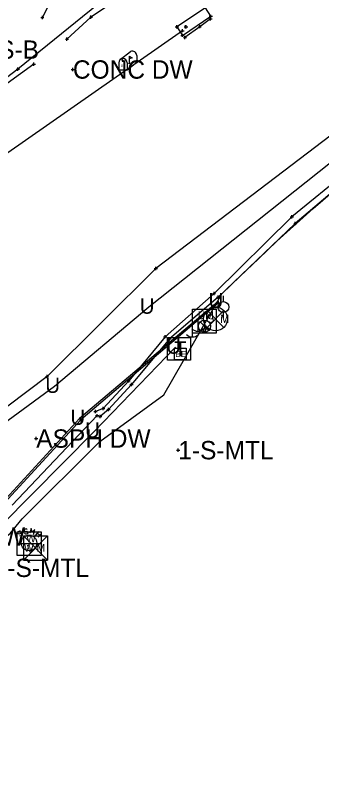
# Model space of a CAD drawing. Extents: x -1 to 1157254, y -1 to 2021979.
# Drawn here: x 1146610.6 to 1146731, y 2016480.3 to 2016780.3 of the extents above; entities that cross this region are included whole.
import ezdxf

# ---------------------------------------------------------------- set-up
doc = ezdxf.new("R2010")
doc.units = 0
for name, color, linetype in [('S_BUILDING_ANNOT', 7, 'Continuous'), ('S_CAL_CORNER', 7, 'Continuous'), ('S_CAL_CORNER_ANNOT', 7, 'Continuous'), ('S_CATCH_BASIN', 7, 'Continuous'), ('S_CATCH_BASIN_ANNOT', 7, 'Continuous'), ('S_CONTOUR_ANNOT', 7, 'Continuous'), ('S_CONTOUR_MAJOR', 7, 'Continuous'), ('S_CROSS_DRAIN', 7, 'Continuous'), ('S_CROSS_DRAIN_ANNOT', 7, 'Continuous'), ('S_CTL_TABLE', 7, 'Continuous'), ('S_DITCHLINE', 7, 'Continuous'), ('S_DRIVEWAY', 7, 'Continuous'), ('S_DRIVEWAY_ANNOT', 7, 'Continuous'), ('S_DROP_INLET', 7, 'Continuous'), ('S_DROP_INLET_ANNOT', 7, 'Continuous'), ('S_EDGE_BITUMINOUS_ANNOT', 7, 'Continuous'), ('S_ELECTRIC_UTILITIES', 7, 'Continuous'), ('S_FENCE', 7, 'Continuous'), ('S_GAS_PUMP_ISLAND_ANNOT', 7, 'Continuous'), ('S_GATE', 7, 'Continuous')]:
    doc.layers.add(name, color=color, linetype=linetype)

msp = doc.modelspace()

# ---------------------------------------------------------------- linework, layer by layer
at = {"layer": 'S_BUILDING_ANNOT'}
for p, q in [((1146686.78, 2016779.94), (1146688.05, 2016779.94)), ((1146687.42, 2016779.3), (1146687.42, 2016780.58)), ((1146687.42, 2016779.94), (1146687.42, 2016779.94)), ((1146673.47, 2016775.77), (1146674.74, 2016775.77)), ((1146674.11, 2016775.13), (1146674.1, 2016776.41)), ((1146674.1, 2016775.77), (1146674.1, 2016775.77)), ((1146676.9, 2016775.8), (1146678.18, 2016775.8)), ((1146677.1, 2016775.77), (1146678.37, 2016775.77)), ((1146677.54, 2016775.16), (1146677.54, 2016776.44)), ((1146677.54, 2016775.8), (1146677.54, 2016775.8)), ((1146677.73, 2016775.14), (1146677.73, 2016776.41)), ((1146677.73, 2016775.77), (1146677.73, 2016775.77)), ((1146675.61, 2016772.46), (1146676.89, 2016772.47)), ((1146675.71, 2016774.31), (1146676.98, 2016774.31)), ((1146676.25, 2016771.83), (1146676.25, 2016773.1)), ((1146676.25, 2016772.46), (1146676.25, 2016772.46)), ((1146676.35, 2016773.67), (1146676.34, 2016774.95)), ((1146676.34, 2016774.31), (1146676.34, 2016774.31)), ((1146610.94, 2016759.23), (1146612.21, 2016759.23)), ((1146611.58, 2016758.59), (1146611.58, 2016759.87)), ((1146611.58, 2016759.23), (1146611.58, 2016759.23)), ((1146632.59, 2016759.06), (1146633.86, 2016759.07)), ((1146633.23, 2016758.43), (1146633.22, 2016759.7)), ((1146633.23, 2016759.07), (1146633.23, 2016759.07)), ((1146718.66, 2016701.25), (1146719.93, 2016701.25)), ((1146719.29, 2016700.61), (1146719.29, 2016701.88)), ((1146719.29, 2016701.25), (1146719.29, 2016701.25)), ((1146720.02, 2016698.6), (1146721.29, 2016698.61)), ((1146720.66, 2016697.97), (1146720.65, 2016699.24)), ((1146720.65, 2016698.61), (1146720.65, 2016698.61)), ((1146665.18, 2016680.99), (1146666.45, 2016681)), ((1146665.82, 2016680.36), (1146665.81, 2016681.63)), ((1146665.82, 2016680.99), (1146665.82, 2016680.99)), ((1146688.06, 2016671.14), (1146689.33, 2016671.15)), ((1146688.7, 2016670.51), (1146688.69, 2016671.78)), ((1146688.69, 2016671.14), (1146688.69, 2016671.14)), ((1146690.36, 2016669.05), (1146690.35, 2016670.33)), ((1146689.72, 2016669.69), (1146690.99, 2016669.69)), ((1146689.81, 2016667.45), (1146691.08, 2016667.46)), ((1146690.36, 2016669.69), (1146690.36, 2016669.69)), ((1146690.44, 2016666.82), (1146690.44, 2016668.09)), ((1146690.44, 2016667.45), (1146690.44, 2016667.45)), ((1146668.85, 2016654.2), (1146670.12, 2016654.2)), ((1146669.49, 2016653.57), (1146669.48, 2016654.84)), ((1146669.49, 2016654.2), (1146669.49, 2016654.2)), ((1146670.57, 2016653.4), (1146671.84, 2016653.4)), ((1146671.21, 2016652.76), (1146671.2, 2016654.04)), ((1146671.2, 2016653.4), (1146671.2, 2016653.4)), ((1146622.43, 2016638.6), (1146623.7, 2016638.6)), ((1146623.06, 2016637.96), (1146623.06, 2016639.23)), ((1146623.06, 2016638.6), (1146623.06, 2016638.6)), ((1146655.16, 2016636.19), (1146655.16, 2016637.46)), ((1146654.52, 2016636.82), (1146655.8, 2016636.83)), ((1146655.16, 2016636.82), (1146655.16, 2016636.82)), ((1146655.67, 2016635.42), (1146656.94, 2016635.42)), ((1146656.3, 2016634.79), (1146656.3, 2016636.06)), ((1146656.3, 2016635.42), (1146656.3, 2016635.42)), ((1146642.12, 2016624.24), (1146642.12, 2016625.51)), ((1146644.54, 2016626.05), (1146645.81, 2016626.05)), ((1146645.18, 2016625.41), (1146645.17, 2016626.68)), ((1146645.17, 2016626.05), (1146645.17, 2016626.05)), ((1146646.6, 2016625.66), (1146647.88, 2016625.66)), ((1146647.24, 2016625.03), (1146647.24, 2016626.3)), ((1146647.24, 2016625.66), (1146647.24, 2016625.66)), ((1146636.41, 2016620.93), (1146636.41, 2016622.2)), ((1146641.49, 2016624.87), (1146642.76, 2016624.88)), ((1146642.12, 2016624.87), (1146642.12, 2016624.87)), ((1146642.17, 2016623.21), (1146643.44, 2016623.21)), ((1146642.81, 2016622.57), (1146642.8, 2016623.85)), ((1146642.8, 2016623.21), (1146642.8, 2016623.21)), ((1146643.35, 2016622.84), (1146644.62, 2016622.84)), ((1146643.98, 2016622.21), (1146643.98, 2016623.48)), ((1146643.98, 2016622.84), (1146643.98, 2016622.84)), ((1146635.77, 2016621.57), (1146637.04, 2016621.57)), ((1146636.41, 2016621.57), (1146636.41, 2016621.57)), ((1146618.19, 2016614.22), (1146619.46, 2016614.23)), ((1146618.83, 2016613.59), (1146618.82, 2016614.86)), ((1146618.82, 2016614.22), (1146618.82, 2016614.22)), ((1146674.65, 2016609.02), (1146674.65, 2016610.29)), ((1146674.01, 2016609.65), (1146675.29, 2016609.66)), ((1146674.65, 2016609.66), (1146674.65, 2016609.66))]:
    msp.add_line(p, q, dxfattribs=at)
at = {"layer": 'S_CAL_CORNER'}
for p, q in [((1146683.28, 2016659.99), (1146686.61, 2016656.65)), ((1146684.79, 2016660.21), (1146685.1, 2016660.21)), ((1146684.95, 2016658.32), (1146684.95, 2016660.05)), ((1146684.95, 2016658.32), (1146684.95, 2016657.26)), ((1146684.35, 2016657.42), (1146684.35, 2016657.23)), ((1146685.54, 2016657.42), (1146685.55, 2016657.19))]:
    msp.add_line(p, q, dxfattribs=at)
msp.add_lwpolyline([(1146680.18, 2016664.98), (1146689.59, 2016664.98), (1146689.59, 2016655.57), (1146680.18, 2016655.57)], close=True, dxfattribs=at)
msp.add_circle((1146684.95, 2016658.32), 2.36, dxfattribs=at)
for centre, radius, start, end in [((1146684.95, 2016660.21), 0.156, 180, 0), ((1146684.77, 2016657.81), 0.58, 223.1344, 287.472), ((1146685.12, 2016657.82), 0.58, 252.528, 316.8656)]:
    msp.add_arc(centre, radius, start, end, dxfattribs=at)
msp.add_ellipse((1146684.95, 2016657.07), major_axis=(0, -0.82), ratio=0.744362, start_param=4.519801, end_param=8.000179, dxfattribs=at)
at = {"layer": 'S_CAL_CORNER_ANNOT'}
for p, q in [((1146685.98, 2016657.87), (1146692.6, 2016664.48)), ((1146685.98, 2016664.48), (1146692.6, 2016657.87))]:
    msp.add_line(p, q, dxfattribs=at)
msp.add_lwpolyline([(1146788.73, 2016902.43), (1146611.58, 2016759.23), (1146520.07, 2016689.4), (1146406.59, 2016626.1)], dxfattribs=at)
msp.add_circle((1146689.29, 2016661.18), 4.68, dxfattribs=at)
at = {"layer": 'S_CATCH_BASIN'}
for p, q in [((1146692.36, 2016667.94), (1146692.36, 2016670.19)), ((1146690.27, 2016665.81), (1146687.95, 2016665.81)), ((1146682.3, 2016661.07), (1146682.3, 2016656.34)), ((1146692.44, 2016661.4), (1146692.44, 2016663.72)), ((1146680.16, 2016658.81), (1146680.16, 2016654.08))]:
    msp.add_line(p, q, dxfattribs=at)
msp.add_circle((1146692.36, 2016665.83), 2.13, dxfattribs=at)
for centre in [(1146680.22, 2016657.51), (1146682.36, 2016659.77)]:
    msp.add_arc(centre, 3.41, 226.3972, 313.6028, dxfattribs=at)
at = {"layer": 'S_CATCH_BASIN_ANNOT'}
msp.add_lwpolyline([(1146670.42, 2016644.93), (1146670.42, 2016653.93), (1146679.42, 2016653.93), (1146679.42, 2016644.93)], close=True, dxfattribs=at)
at = {"layer": 'S_CONTOUR_ANNOT'}
for p, q in [((1146611.33, 2016577.67), (1146620.74, 2016577.67)), ((1146611.33, 2016568.26), (1146611.33, 2016577.67)), ((1146620.74, 2016577.67), (1146620.74, 2016568.26)), ((1146613.86, 2016576.02), (1146623.2, 2016576.02)), ((1146613.86, 2016576.02), (1146613.86, 2016566.53)), ((1146613.86, 2016576.02), (1146623.2, 2016566.53)), ((1146623.2, 2016576.02), (1146613.86, 2016566.53)), ((1146623.2, 2016576.02), (1146623.2, 2016566.53)), ((1146611.33, 2016572.99), (1146620.74, 2016572.99)), ((1146620.74, 2016568.26), (1146611.33, 2016568.26)), ((1146613.86, 2016566.53), (1146623.2, 2016566.53))]:
    msp.add_line(p, q, dxfattribs=at)
at = {"layer": 'S_CROSS_DRAIN'}
for p, q in [((1146651.78, 2016762.97), (1146655.91, 2016766.08)), ((1146655.39, 2016764.26), (1146655.39, 2016761.54)), ((1146658.34, 2016764.6), (1146658.34, 2016761.89)), ((1146651.23, 2016761.69), (1146651.23, 2016758.98)), ((1146654.55, 2016758.98), (1146658.34, 2016761.89)), ((1146654.55, 2016761.69), (1146654.55, 2016758.98)), ((1146651.23, 2016758.98), (1146654.55, 2016758.98))]:
    msp.add_line(p, q, dxfattribs=at)
for points in [[(1146655.39, 2016764.26), (1146656.5, 2016763.59), (1146655.39, 2016763.25)], [(1146652.41, 2016762.81), (1146652.63, 2016762.67), (1146652.63, 2016762.28), (1146652.94, 2016762.28), (1146652.94, 2016762.64), (1146652.74, 2016762.89), (1146652.41, 2016762.84)]]:
    msp.add_lwpolyline(points, dxfattribs=at)
for centre, end in [((1146656.68, 2016764.6), 117.5718), ((1146652.89, 2016761.69), 180)]:
    msp.add_arc(centre, 1.66, 0, end, dxfattribs=at)
msp.add_ellipse((1146655.39, 2016761.54), major_axis=(0.145, 0.132), ratio=0.564646, dxfattribs=at)
at = {"layer": 'S_CROSS_DRAIN_ANNOT'}
msp.add_lwpolyline([(1146673.19, 2016645.15), (1146673.19, 2016649.65), (1146677.69, 2016649.65), (1146677.69, 2016645.15)], close=True, dxfattribs=at)
at = {"layer": 'S_CTL_TABLE'}
for p, q in [((1146620.59, 2016779.5), (1146621.86, 2016779.5)), ((1146621.23, 2016778.86), (1146621.22, 2016780.14)), ((1146621.23, 2016779.5), (1146621.23, 2016779.5)), ((1146639.71, 2016779.66), (1146640.98, 2016779.66)), ((1146640.34, 2016779.02), (1146640.34, 2016780.3)), ((1146640.34, 2016779.66), (1146640.34, 2016779.66)), ((1146686.69, 2016778.92), (1146687.96, 2016778.93)), ((1146687.33, 2016778.29), (1146687.33, 2016779.56)), ((1146687.33, 2016778.93), (1146687.33, 2016778.93)), ((1146682.43, 2016775.87), (1146683.7, 2016775.87)), ((1146683.07, 2016775.23), (1146683.07, 2016776.51)), ((1146683.07, 2016775.87), (1146683.07, 2016775.87)), ((1146677.28, 2016770.99), (1146677.27, 2016772.26)), ((1146630.26, 2016770.98), (1146631.54, 2016770.98)), ((1146630.9, 2016770.35), (1146630.9, 2016771.62)), ((1146630.9, 2016770.98), (1146630.9, 2016770.98)), ((1146676.64, 2016771.62), (1146677.91, 2016771.63)), ((1146677.28, 2016771.62), (1146677.28, 2016771.62)), ((1146617.21, 2016761.13), (1146618.48, 2016761.13)), ((1146617.85, 2016760.49), (1146617.84, 2016761.77)), ((1146617.85, 2016761.13), (1146617.85, 2016761.13))]:
    msp.add_line(p, q, dxfattribs=at)
at = {"layer": 'S_DITCHLINE'}
msp.add_lwpolyline([(1146676.34, 2016774.31), (1146474.52, 2016633.57)], dxfattribs=at)
at = {"layer": 'S_DRIVEWAY'}
for p, q in [((1146611.66, 2016577.56), (1146611.59, 2016577.17)), ((1146611.59, 2016577.17), (1146611.78, 2016576.9)), ((1146612.2, 2016577.94), (1146611.66, 2016577.56)), ((1146612.63, 2016577.87), (1146612.2, 2016577.94)), ((1146612.2, 2016576.78), (1146612.75, 2016577.13)), ((1146612.75, 2016577.13), (1146613.21, 2016577.05)), ((1146613.21, 2016577.05), (1146613.37, 2016576.78)), ((1146618.63, 2016576.32), (1146619.87, 2016577.79)), ((1146619.29, 2016577.09), (1146620.26, 2016576.28)), ((1146611.78, 2016576.9), (1146612.2, 2016576.78)), ((1146612.75, 2016575.97), (1146612.36, 2016576.05)), ((1146613.29, 2016576.36), (1146612.75, 2016575.97)), ((1146613.37, 2016576.78), (1146613.29, 2016576.36)), ((1146620.84, 2016576.98), (1146619.6, 2016575.5))]:
    msp.add_line(p, q, dxfattribs=at)
for points in [[(1146615.3, 2016578.49), (1146614.96, 2016578.76), (1146614.3, 2016578.68), (1146614.06, 2016578.33), (1146614.1, 2016578.02), (1146614.45, 2016577.71), (1146615.07, 2016577.83), (1146615.46, 2016577.52), (1146615.5, 2016577.21), (1146615.23, 2016576.82), (1146614.61, 2016576.74), (1146614.26, 2016577.01)], [(1146617.74, 2016576.63), (1146618.29, 2016578.49), (1146617.24, 2016577.48), (1146616.85, 2016578.91), (1146616.31, 2016577.05)]]:
    msp.add_lwpolyline(points, dxfattribs=at)
msp.add_circle((1146615.99, 2016573.26), 3.05, dxfattribs=at)
at = {"layer": 'S_DRIVEWAY_ANNOT'}
for points in [[(1146807.18, 2016779.61), (1146804.98, 2016778.17), (1146793.16, 2016770), (1146777.58, 2016755.69), (1146759.35, 2016738.82), (1146741.21, 2016719.06), (1146719.29, 2016701.25), (1146688.69, 2016671.14), (1146669.49, 2016654.2), (1146655.16, 2016636.82), (1146645.17, 2016626.05), (1146642.12, 2016624.87)], [(1146806.76, 2016777.3), (1146804.54, 2016775.7), (1146794.25, 2016768.67), (1146778.6, 2016754.59), (1146760.98, 2016736.98), (1146742.9, 2016717.49), (1146720.65, 2016698.61), (1146690.36, 2016669.69), (1146671.2, 2016653.4), (1146656.3, 2016635.42), (1146647.24, 2016625.66), (1146643.98, 2016622.84)]]:
    msp.add_lwpolyline(points, dxfattribs=at)
at = {"layer": 'S_DROP_INLET'}
for points in [[(1148195.53, 2017935.77), (1148138.82, 2017892.99), (1148034.43, 2017809.59), (1147909.47, 2017714.32), (1147828.88, 2017654.71), (1147681.29, 2017538.62), (1147545.03, 2017424.01), (1147436.65, 2017326.84), (1147356.29, 2017257.74), (1147237.67, 2017148.84), (1147152.37, 2017082.27), (1147079.41, 2017020.24), (1146950.46, 2016911.58), (1146849.38, 2016826.65), (1146763.18, 2016745.2), (1146663.11, 2016665.75), (1146626.02, 2016634.68), (1146520.54, 2016557.46), (1146484.38, 2016531.03)], [(1146690.18, 2016667.93), (1146635.88, 2016622.11), (1146544.84, 2016523.22), (1146493.62, 2016472.25), (1146496.51, 2016468.3)], [(1146673.52, 2016650.06), (1146641.67, 2016617.07), (1146543.75, 2016518.41), (1146444.99, 2016418.15), (1146374.63, 2016345.67)]]:
    msp.add_lwpolyline(points, dxfattribs=at)
at = {"layer": 'S_DROP_INLET_ANNOT'}
msp.add_lwpolyline([(1146642.8, 2016623.21), (1146609.35, 2016588.04)], dxfattribs=at)
at = {"layer": 'S_EDGE_BITUMINOUS_ANNOT'}
for points in [[(1146710.47, 2016862.46), (1146683.2, 2016838.78), (1146659.49, 2016814.67), (1146628.05, 2016793.57), (1146621.23, 2016779.5)], [(1146721.89, 2016845.46), (1146699.19, 2016828.64), (1146669.8, 2016799.26), (1146640.34, 2016779.66), (1146630.9, 2016770.98)], [(1146687.33, 2016778.93), (1146683.07, 2016775.87), (1146677.28, 2016771.62)], [(1146617.85, 2016761.13), (1146596.76, 2016746.01), (1146596.15, 2016741.34), (1146575.37, 2016726.8), (1146546.92, 2016708.8), (1146518.5, 2016689.65), (1146497.26, 2016674.6), (1146467.54, 2016653), (1146436.53, 2016629.8), (1146408.82, 2016609.98), (1146388.84, 2016601.11), (1146355.38, 2016578.55), (1146316.44, 2016549.94), (1146267.98, 2016522.51), (1146251.21, 2016522.77), (1146225.59, 2016506.15), (1146208.66, 2016490.65)]]:
    msp.add_lwpolyline(points, dxfattribs=at)
at = {"layer": 'S_ELECTRIC_UTILITIES'}
msp.add_lwpolyline([(1146687.42, 2016779.94), (1146685.39, 2016783.28), (1146674.1, 2016775.77), (1146676.25, 2016772.46)], close=True, dxfattribs=at)
at = {"layer": 'S_FENCE'}
for points in [[(1148182.05, 2017918.06), (1148146.03, 2017882.74), (1148036.88, 2017800.65), (1147915.13, 2017710.9), (1147841.97, 2017653.39), (1147689.75, 2017529.1), (1147550.85, 2017419.33), (1147452.64, 2017321.35), (1147370.71, 2017243.52), (1147258.33, 2017138.3), (1147166.15, 2017078.02), (1147070.18, 2016992.83), (1146962.81, 2016905.87), (1146854.86, 2016827.91), (1146747.33, 2016742.81), (1146665.82, 2016680.99), (1146623.06, 2016638.6), (1146514.26, 2016556.71), (1146391.39, 2016471.4), (1146322.08, 2016427.51), (1146235.84, 2016374), (1146176.66, 2016335.01), (1146181.42, 2016326.5)], [(1146690.44, 2016667.45), (1146636.41, 2016621.57), (1146545.52, 2016523.15), (1146438.63, 2016422.41), (1146376.05, 2016354.06)]]:
    msp.add_lwpolyline(points, dxfattribs=at)
at = {"layer": 'S_GAS_PUMP_ISLAND_ANNOT'}
msp.add_lwpolyline([(1146496.98, 2016475.35), (1146503.99, 2016482.47), (1146511, 2016489.6), (1146518, 2016496.72), (1146531.83, 2016510.46), (1146539, 2016517.42), (1146546.18, 2016524.37), (1146554.1, 2016532.04), (1146561.35, 2016538.92), (1146568.6, 2016545.8), (1146575.86, 2016552.68), (1146608.62, 2016576.91), (1146613.32, 2016582.73), (1146643.88, 2016613.13), (1146668.98, 2016631.33), (1146691.72, 2016671), (1146698.96, 2016677.9), (1146706.19, 2016684.8), (1146713.42, 2016691.7), (1146727.66, 2016704.55), (1146735.28, 2016711.02)], dxfattribs=at)

# ---------------------------------------------------------------- texts
at = {"layer": 'S_CAL_CORNER'}
msp.add_text('UM', height=2.999, dxfattribs=at).set_placement((1146682.33, 2016661.1))
at = {"layer": 'S_CAL_CORNER_ANNOT'}
for s, p in [('G', (1146685.47, 2016659.71)), ('M', (1146691.04, 2016659.61))]:
    msp.add_text(s, height=3.3, dxfattribs=at).set_placement(p)
at = {"layer": 'S_CATCH_BASIN_ANNOT'}
msp.add_text('T', height=6, dxfattribs=at).set_placement((1146672.99, 2016646.43))
at = {"layer": 'S_CONTOUR_ANNOT'}
for s, height, p in [('W', 3, (1146614.88, 2016573.52)), ('W M', 2.999, (1146614.07, 2016569.79)), ('V', 3, (1146615.11, 2016569.46))]:
    msp.add_text(s, height=height, dxfattribs=at).set_placement(p)
at = {"layer": 'S_CONTOUR_MAJOR'}
for p in [(1146686.55, 2016665.38), (1146659.49, 2016663.21), (1146669.89, 2016647.51), (1146622.39, 2016632.14), (1146632.25, 2016619.56), (1146638.04, 2016614.53)]:
    msp.add_text('U', height=6, dxfattribs=at).set_placement(p)
at = {"layer": 'S_CROSS_DRAIN'}
msp.add_text('US', height=0.96, dxfattribs=at).set_placement((1146651.99, 2016760.17))
at = {"layer": 'S_CROSS_DRAIN_ANNOT'}
msp.add_text('BE', height=2.399, dxfattribs=at).set_placement((1146673.51, 2016646.2))
at = {"layer": 'S_GATE'}
for s, p in [('1-S-B', (1146595.27, 2016763.27)), ('CONC DW', (1146633.23, 2016755.47)), ('ASPH DW', (1146618.82, 2016610.62)), ('1-S-MTL', (1146674.65, 2016606.06)), ('GRVL DW', (1146569.54, 2016572.24)), ('1-S-MTL', (1146602.13, 2016559.89))]:
    msp.add_text(s, height=7.2, dxfattribs=at).set_placement(p)

doc.saveas('drawing.dxf')
